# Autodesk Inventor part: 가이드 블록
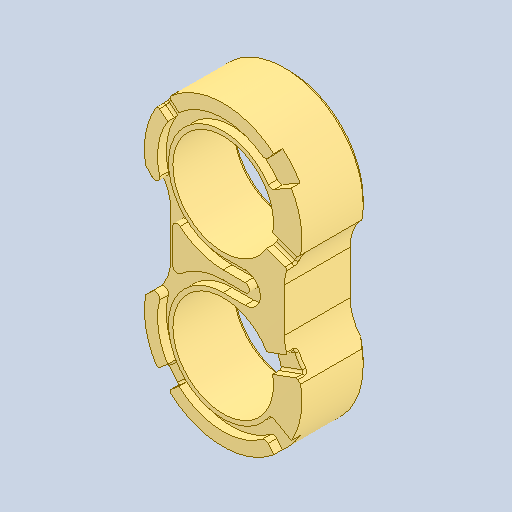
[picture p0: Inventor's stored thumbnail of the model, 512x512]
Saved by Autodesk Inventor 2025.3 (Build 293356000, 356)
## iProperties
Created: 2025-10
Part Number: 가이드 블록
Material: 강철, 주조
Document SubType Name: Modeling
Designer: PC-04
Density: 7.85 g/cm^3
Appearance: 기본값
Author: jhkim
Sending System: Autodesk Inventor 2026
Preprocessor: ST-DEVELOPER v20.1
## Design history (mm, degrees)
feature "솔리드1"
node "솔리드2"
